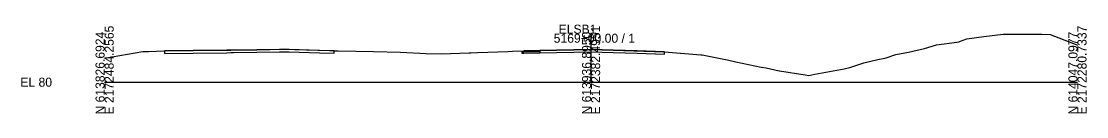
# Model space of a CAD drawing. Extents: x -26 to 1303, y -3010 to 12033.
# Drawn here: x -25.7 to 302.8, y -1509.7 to -1482.2 of the extents above; entities that cross this region are included whole.
import ezdxf

# ---------------------------------------------------------------- set-up
doc = ezdxf.new("R2010")
doc.units = 0
for name, color, linetype in [('RD_GPK_XS_Cell', 7, 'Continuous'), ('RD_XS_Base', 7, 'Continuous'), ('RD_XS_ExGround', 7, 'Continuous'), ('RD_XS_ExPaveRet', 7, 'Continuous'), ('RD_XS_Pave', 7, 'Continuous'), ('RD_XS_PaveOvlay_CP', 7, 'Continuous')]:
    doc.layers.add(name, color=color, linetype=linetype)

msp = doc.modelspace()

# ---------------------------------------------------------------- linework, layer by layer
at = {"layer": 'RD_GPK_XS_Cell'}
for p, q in [((150, -1500), (150, -1485)), ((0, -1500), (150, -1500)), ((150, -1500), (300, -1500))]:
    msp.add_line(p, q, dxfattribs=at)
at = {"layer": 'RD_XS_Base'}
for p, q in [((128.72, -1491.15), (128.72, -1491.15)), ((128.72, -1491.15), (128.72, -1491.15)), ((128.73, -1490.65), (129.23, -1490.63)), ((128.73, -1491.15), (128.73, -1490.65)), ((128.73, -1490.65), (128.73, -1490.65)), ((129.22, -1491.13), (128.73, -1491.15)), ((134.17, -1490.98), (129.22, -1491.13)), ((129.22, -1491.13), (129.22, -1491.13)), ((129.23, -1490.63), (134.17, -1490.48)), ((129.23, -1490.63), (129.23, -1490.63)), ((134.17, -1490.92), (134.17, -1490.98))]:
    msp.add_line(p, q, dxfattribs=at)
at = {"layer": 'RD_XS_ExGround'}
msp.add_lwpolyline([(0, -1492.62), (2.34, -1492.18), (11.82, -1490.56), (13.51, -1490.5), (18.45, -1490.33), (27.33, -1490.24), (38.95, -1490.11), (46.94, -1489.98), (55.03, -1489.83), (69.32, -1490.23), (70.81, -1490.28), (72.02, -1490.3), (82.96, -1490.51), (91.27, -1490.74), (99.19, -1491.08), (103.8, -1491.27), (112.44, -1490.94), (112.57, -1490.94), (112.96, -1490.92), (114.94, -1490.85), (124.46, -1490.5), (125.78, -1490.45), (129.43, -1490.31), (132.16, -1490.23), (134.17, -1490.17), (139.37, -1490.06), (150.05, -1489.84), (156.78, -1490.05), (172.69, -1490.58), (183.85, -1491.49), (183.99, -1491.5), (184.26, -1491.55), (192.48, -1493.18), (194.68, -1493.74), (202.44, -1495.32), (203.99, -1495.55), (208.03, -1496.51), (208.15, -1496.54), (216.03, -1497.73), (217.17, -1497.89), (219.05, -1497.52), (228.03, -1495.91), (229.75, -1495.48), (234.11, -1494.02), (238.47, -1492.94), (240.61, -1492.62), (240.97, -1492.48), (243.96, -1491.45), (247.87, -1490.75), (252.86, -1489.61), (256.5, -1488.48), (262.79, -1487.57), (263.5, -1487.47), (263.6, -1487.45), (265.88, -1486.58), (271.12, -1485.85), (277.08, -1485.18), (288.97, -1485.15), (291.55, -1485.22), (298.8, -1488.07), (300, -1488.54)], dxfattribs=at)
at = {"layer": 'RD_XS_ExPaveRet'}
for p, q in [((37.7, -1490.13), (27.33, -1490.24)), ((38.95, -1490.11), (37.7, -1490.13)), ((39.81, -1490.1), (38.95, -1490.11)), ((55.03, -1489.83), (53.95, -1489.85)), ((60.02, -1489.97), (60, -1489.97)), ((172.68, -1490.58), (164.23, -1490.3)), ((172.69, -1490.58), (172.68, -1490.58))]:
    msp.add_line(p, q, dxfattribs=at)
for points in [[(60, -1489.97), (56.94, -1489.89), (55.03, -1489.83), (53.95, -1489.85), (46.94, -1489.98), (39.81, -1490.1), (38.95, -1490.11), (37.7, -1490.13), (27.33, -1490.24), (18.45, -1490.33), (18.45, -1490.33), (18.45, -1490.33), (18.45, -1490.33), (18.45, -1490.33), (18.45, -1490.33), (18.45, -1490.72), (18.45, -1491.08), (18.45, -1491.08), (18.45, -1491.08), (18.45, -1491.08), (18.45, -1491.08), (18.45, -1491.08), (27.33, -1490.99), (37.7, -1490.88), (38.95, -1490.86), (39.81, -1490.85), (46.94, -1490.73), (53.95, -1490.6), (55.03, -1490.58), (56.94, -1490.64), (60, -1490.72), (66.27, -1490.9), (70.81, -1491.03), (70.81, -1490.66), (70.81, -1490.28), (66.27, -1490.15), (60, -1489.97)], [(18.45, -1490.33), (18.45, -1490.72), (18.45, -1491.08), (18.45, -1491.08), (18.45, -1491.08), (18.45, -1491.08), (27.33, -1490.99), (37.7, -1490.88), (38.95, -1490.86), (39.81, -1490.85), (46.94, -1490.73), (53.95, -1490.6), (55.03, -1490.58), (56.94, -1490.64), (60, -1490.72), (66.27, -1490.9), (70.81, -1491.03), (70.81, -1490.66), (70.81, -1490.28), (66.27, -1490.15), (60.02, -1489.97)], [(27.33, -1490.24), (18.45, -1490.33), (18.45, -1490.33), (18.45, -1490.33), (18.45, -1490.33), (18.45, -1490.33)], [(53.95, -1489.85), (46.94, -1489.98), (39.81, -1490.1)], [(60, -1489.97), (56.94, -1489.89), (55.03, -1489.83)], [(172.69, -1490.58), (172.69, -1490.58), (172.69, -1490.58), (172.68, -1490.58), (164.23, -1490.3), (156.78, -1490.05), (150.07, -1489.85), (150.05, -1489.84), (150, -1489.85), (139.37, -1490.06), (134.17, -1490.17), (134.17, -1490.67), (134.17, -1490.92), (139.37, -1490.81), (150, -1490.6), (150.05, -1490.59), (150.07, -1490.6), (156.78, -1490.8), (164.23, -1491.05), (172.68, -1491.33), (172.69, -1491.33), (172.69, -1491.33), (172.69, -1491.33), (172.69, -1491.33), (172.69, -1491.08), (172.69, -1490.58), (172.69, -1490.58)], [(150.05, -1489.84), (150, -1489.85), (139.37, -1490.06), (139.37, -1490.06), (134.17, -1490.17)], [(134.17, -1490.17), (134.17, -1490.67), (134.17, -1490.92), (139.37, -1490.81), (150, -1490.6), (150.05, -1490.59), (150.07, -1490.6), (156.78, -1490.8), (164.23, -1491.05), (172.68, -1491.33), (172.69, -1491.33), (172.69, -1491.33), (172.69, -1491.33), (172.69, -1491.08), (172.69, -1490.58), (172.69, -1490.58), (172.69, -1490.58)], [(164.23, -1490.3), (156.78, -1490.05), (150.07, -1489.85), (150.05, -1489.84)]]:
    msp.add_lwpolyline(points, dxfattribs=at)
at = {"layer": 'RD_XS_Pave'}
for p, q in [((134.17, -1490.17), (129.23, -1490.32)), ((129.23, -1490.32), (129.23, -1490.32)), ((129.23, -1490.32), (129.23, -1490.47)), ((134.17, -1490.33), (129.23, -1490.47)), ((129.23, -1490.47), (134.17, -1490.33)), ((129.23, -1490.47), (129.23, -1490.47)), ((129.23, -1490.47), (129.23, -1490.63)), ((129.23, -1490.47), (129.23, -1490.47)), ((129.23, -1490.47), (129.23, -1490.47)), ((129.23, -1490.63), (134.17, -1490.48)), ((129.23, -1490.63), (129.23, -1490.63)), ((129.23, -1490.63), (129.23, -1490.63))]:
    msp.add_line(p, q, dxfattribs=at)
at = {"layer": 'RD_XS_PaveOvlay_CP'}
for p in [(134.17, -1490.17), (129.23, -1490.32)]:
    msp.add_line(p, (129.23, -1490.32), dxfattribs=at)

# ---------------------------------------------------------------- texts
at = {"layer": 'RD_GPK_XS_Cell'}
for s, p in [('N 613826.6924', (0, -1510)), ('E 2172484.2565', (2.8, -1510)), ('N 613936.8950', (150, -1510)), ('E 2172382.4951', (152.8, -1510)), ('N 614047.0977', (300, -1510)), ('E 2172280.7337', (302.8, -1510))]:
    msp.add_text(s, height=2.8, rotation=90, dxfattribs=at).set_placement(p)
for s, p in [('5169+00.00 / 1', (138.48, -1487.8)), ('ELSB1', (140, -1485)), ('EL 80', (-26, -1501.4))]:
    msp.add_text(s, height=2.8, dxfattribs=at).set_placement(p)

doc.saveas('drawing.dxf')
